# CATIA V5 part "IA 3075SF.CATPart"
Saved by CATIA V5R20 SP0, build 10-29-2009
Part number: IA 3075SF
Revision: ANY
Definition: UNKNOWN
Nomenclature: IA 3075SF
Source: Unknown
Bounding box of the stored display mesh (mm): x -1.5 to 1.5, y -2.85 to 4.9, z -1.5 to 1.5
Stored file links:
  C:\Users\Utente\Desktop\IO LAVORO\3D X SITO CF\CUMSA\3D files FA\FA 0530SF\IA 3075SF.CATPart

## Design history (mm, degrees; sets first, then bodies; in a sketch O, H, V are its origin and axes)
Body1 "Cortar-Extruir1" (main body)
  Solid1: solid without history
